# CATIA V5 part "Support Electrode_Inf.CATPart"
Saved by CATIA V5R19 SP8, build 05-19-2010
Part number: Support Electrode_Inf
Nomenclature: 65
Bounding box of the stored display mesh (mm): x -57.5 to 57.5, y -20 to 20, z 0 to 20
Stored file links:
  C:\Users\rphgr\Desktop\0_Tapis_TC520B_vitesse\Support Electrode_Inf.CATPart
  D:\Documents\1_Travail\1 - ac-limoges.fr\ac-limoges.fr\Emmanuel Maynard - STI2D_Turgot\3 - Supports\Tapis de course TC520B\Tapis de course TC520B_Ca\0_Tapis_TC520B_Conception.CATProduct
  D:\Documents\1_Travail\1 - ac-limoges.fr\ac-limoges.fr\Emmanuel Maynard - STI2D_Turgot\3 - Supports\Tapis de course TC520B\Tapis de course TC520B_Ca\Tapis.CATPart
  D:\Documents\1_Travail\1 - ac-limoges.fr\ac-limoges.fr\Emmanuel Maynard - STI2D_Turgot\3 - Supports\Tapis de course TC520B\Tapis de course TC520B_Ca\Guidon.CATPart
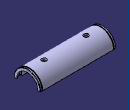
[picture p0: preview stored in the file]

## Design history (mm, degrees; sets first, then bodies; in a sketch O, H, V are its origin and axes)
AxisSystem1: origin (0, 0, 0), X (1, 0, 0), Y (0, 1, 0), Z (0, 0, 1)
Set1
  DatumCurve1
Body1 (main body)
  Sketch1 on ZX plane of AxisSystem1, origin (0, 0, 0), H (0, 0, 1), V (1, 0, 0)
    axis line L1 (0, 0) -> (0, 74.1525)
    point P2 (17, 0)
    line L2 (17, 0) -> (17, 54.5)
    line L3 (17, 54.5) -> (16, 54.5)
    line L4 (16, 54.5) -> (16, 57.5)
    line L5 (16, 57.5) -> (20, 57.5)
    line L6 (20, 57.5) -> (20, 55)
    point P7 (20, 0)
    line L7 (20, 0) -> (17, 0)
    line L8 (19.5, 55) -> (20, 55)
    line L9 (20, 54) -> (19.5, 54)
    line L10 (19.5, 54) -> (19.5, 55)
    line L11 (20, 54) -> (20, 0)
    distance L4 L1 = 16
    distance L4 L2 = 1
    distance L6 L1 = 20
    distance L5 L3 = 3
    distance L5 L7 = 57.5
    distance L8 L5 = 2.5
    distance L8 L9 = 1
    distance L10 L6 = 0.5
    vertical: L1 V, L2 V, L4 V, L6 V, L10 V, L11 V
    coincidence: P2 H, P7 H, L6 L11
    horizontal: L3 H, L5 H, L7 H, L8 H, L9 H
  Shaft1: profile Sketch1, axis Sketch1.L1, angle 90
  Plane1: type Offset, RefPlane XY plane of AxisSystem1, Offset 24
  Sketch2 on face of Shaft1, origin (0, 0, 0), H (1, 0, 0), V (0, -1, 0)
    projected line E1 (54.5, 16) -> (54.5, 17) from edge [face of Shaft1 | face of Shaft1 from Sketch1.L3]
    projected line E2 (54.5, 17) -> (0, 17) from edge [face of Shaft1 | face of Shaft1 from Sketch1.L2]
  Pocket1: profile Sketch2, direction (0, 0, 1), length 2, thin wall 1, second thickness 1.3
  Fillet1: radius 0.5, on edge [face of Shaft1 from Sketch1.L6 | face of Shaft1 from Sketch1.L5]
  Sketch3 on face of Shaft1, origin (0, 0, 0), H (1, 0, 0), V (0, -1, 0)
    point P1 (0, 16.8373)
    line L1 (0, 16.8373) -> (6, 16.8373)
    line L2 (6, 16.8373) -> (6, 15.7315)
    line L3 (6, 15.7315) -> (0, 15.7315)
    line L4 (0, 15.7315) -> (0, 16.8373)
    point P5 (16, 16.8373)
    line L5 (16, 16.8373) -> (28, 16.8373)
    line L6 (28, 16.8373) -> (28, 15.7315)
    line L7 (28, 15.7315) -> (16, 15.7315)
    line L8 (16, 15.7315) -> (16, 16.8373)
    point P7 (28, 15.7315)
    point P9 (38, 16.8373)
    line L9 (38, 16.8373) -> (50, 16.8373)
    line L10 (50, 16.8373) -> (50, 15.7315)
    line L11 (50, 15.7315) -> (38, 15.7315)
    line L12 (38, 15.7315) -> (38, 16.8373)
    point P11 (50, 15.7315)
    distance L12 P11 = 12
    distance L6 L8 = 12
    distance L2 L4 = 6
    distance L2 L8 = 10
    distance L6 L12 = 10
    coincidence: P1 V, P5 L1, P7 L3, P9 L1, P11 L3
    horizontal: L1 H, L3 H, L5 H, L7 H, L9 H, L11 H
    vertical: L2 V, L4 V, L6 V, L8 V, L10 V, L12 V
  Pad1: profile Sketch3, direction (0, 0, -1), up to face of Shaft1 from Sketch1.L2
  Mirror1: of the body so far, about face of Shaft1
  Sketch4 on xy-plane, origin (0, 0, 0), H (1, 0, 0), V (0, 1, 0)
    circle A1 centre (32, 0) radius 5
    point P1 (32, 0)
    reference projected point E1 (32, 0) from edge of DatumCurve1
    radius A1 = 5
    coincidence: P1 H
    concentricity: A1 E1
  Pad2: profile Sketch4, direction (0, 0, 1), up to face of Shaft1 from Sketch1.L2, opposite side length -15.7
  Sketch5 on start face of Pad2, origin (0, 0, 15.7), H (1, 0, 0), V (0, -1, 0)
    circle A1 centre (32, 0) radius 3.5
    point P2 (35.5, 0)
    reference projected circle E1 centre (32, 0) radius 5 from edge [start face of Pad2 | face of Pad2 from Sketch4.A1]
    radius A1 = 3.5
    coincidence: A1 P2, P2 H
    concentricity: A1 E1
  Pad3: profile Sketch5, direction (0, 0, -1), length 6
  Sketch6 on {plane type Tangent, Support face of Shaft1, RefPoint {point type OnSurface, Support face of Shaft1, RefPoint {point stored without definition}, Length 0, Direction (0, 1000, 0)}}, origin (27.7614, 0, 20), H (1, 0, 0), V (0, -1, 0)
    point P1 (4.2386, 0)
    reference projected point E1 (4.2386, 0) from axis of face of Pad3 from Sketch5.A1
    coincidence: P1 E1
  Hole1: placed by Sketch6, at (32, 0, 20) direction (0, 0, -1), diameter 3.3, through (limit type 3), counterbore diameter 7, counterbore depth 3
  Mirror2: of the body so far, about face of Pad1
